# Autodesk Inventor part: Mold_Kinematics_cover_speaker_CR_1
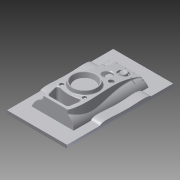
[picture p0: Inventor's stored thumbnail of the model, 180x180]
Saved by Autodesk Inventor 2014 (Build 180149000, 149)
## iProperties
Created: 2009-12
Part Number: Mold_Kinematics_cover_speaker_CR_1
Document SubType Name: Modeling
Designer: gaom
Density: 1 g/cm^3
Material: Generic
Appearance: Default
Author: gaom
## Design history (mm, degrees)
node "Mold_Kinematics_cover_speaker_CR_Base"
feature "Solid1::Mold_Kinematics_cover_speaker_CR_Base"
tag "TaggingFeature1"
body "Solid1"
